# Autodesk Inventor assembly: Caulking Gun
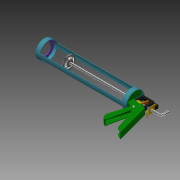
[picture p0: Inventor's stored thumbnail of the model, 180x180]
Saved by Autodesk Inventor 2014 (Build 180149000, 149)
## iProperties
Created: 2009-03
Part Number: Caulking Gun
Document SubType Name: Assembly
Designer: tangg
Mass: 1178.56 g
Surface Area: 1624.46 cm^2
Volume: 273.486 cm^3
Density: 4.30939 g/cm^3
Author: tangg
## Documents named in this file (13)
- C:\Users\iTools\Desktop\tutorial files\Stress Analysis Contacts\Caulk Gun.iam
- C:\Users\iTools\Desktop\tutorial files\Stress Analysis Contacts\Plunger.ipt
- C:\Users\iTools\Desktop\tutorial files\Stress Analysis Contacts\Main Frame.ipt
- C:\Users\iTools\Desktop\tutorial files\Stress Analysis Contacts\Handle.ipt
- C:\Users\iTools\Desktop\tutorial files\Stress Analysis Contacts\Trigger.ipt
- C:\Users\iTools\Desktop\tutorial files\Stress Analysis Contacts\Actuator.ipt
- C:\Users\iTools\Desktop\tutorial files\Stress Analysis Contacts\Caulk Tube.ipt
- C:\Users\iTools\Desktop\tutorial files\Stress Analysis Contacts\Pin.ipt
- C:\Users\iTools\Desktop\tutorial files\Stress Analysis Contacts\Actuator Spring.ipt
- C:\Users\iTools\Desktop\tutorial files\Stress Analysis Contacts\Front Frame.ipt
- C:\Users\iTools\Desktop\tutorial files\Stress Analysis Contacts\Ring.ipt
- C:\Users\iTools\Desktop\tutorial files\Stress Analysis Contacts\Lock.ipt
- C:\Users\iTools\Desktop\tutorial files\Stress Analysis Contacts\Lock Spring.ipt
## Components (12 placed, 12 different names)
1. Main Frame:1 — Flush:1, Flush:2, Flush:3, Mate:30, Flush:5, Mate:44, Flush:11, Mate:54, Mate:57, Flush:15
2. Front Frame:1 — Mate:39, Flush:11, Mate:51, Mate:58
3. Caulk Tube:1 — Mate:31
4. Handle:1 — Flush:2, Mate:27, Mate:33, Flush:5, Mate:39
5. Plunger:1 — Flush:1, Mate:27, Mate:30, Mate:31, Flush:8, Mate:43, Flush:14, Mate:49, Mate:50, Mate:53, Mate:56
6. Trigger:1 — Flush:3, Mate:34, Tangent:1, Mate:59
7. Pin:1 — Mate:33, Mate:34, Mate:59
8. Actuator:1 — Tangent:1, Flush:14, Mate:49, Mate:50
9. Actuator Spring:1 — Mate:43, Mate:44
10. Ring:1 — Mate:51, Mate:58
11. Lock:1 — Mate:56, Mate:57, Flush:15
12. Lock Spring:2 — Mate:53, Mate:54
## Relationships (26: Mate 17, Flush 8, Tangent 1)
- Flush:1: Main Frame:1 ↔ Plunger:1
- Flush:2: Main Frame:1 ↔ Handle:1
- Flush:3: Main Frame:1 ↔ Trigger:1
- Mate:27: Handle:1 ↔ Plunger:1
- Mate:30: Main Frame:1 ↔ Plunger:1
- Mate:31: Caulk Tube:1 ↔ Plunger:1
- Mate:33: Handle:1 ↔ Pin:1
- Mate:34: Trigger:1 ↔ Pin:1
- Flush:5: Main Frame:1 ↔ Handle:1
- Flush:8: Plunger:1
- Mate:39: Front Frame:1 ↔ Handle:1
- Mate:43: Plunger:1 ↔ Actuator Spring:1
- Mate:44: Main Frame:1 ↔ Actuator Spring:1
- Flush:11: Main Frame:1 ↔ Front Frame:1
- Tangent:1: Trigger:1 ↔ Actuator:1
- Flush:14: Plunger:1 ↔ Actuator:1
- Mate:49: Plunger:1 ↔ Actuator:1
- Mate:50: Plunger:1 ↔ Actuator:1
- Mate:51: Front Frame:1 ↔ Ring:1
- Mate:53: Plunger:1 ↔ Lock Spring:2
- Mate:54: Main Frame:1 ↔ Lock Spring:2
- Mate:56: Plunger:1 ↔ Lock:1
- Mate:57: Main Frame:1 ↔ Lock:1
- Flush:15: Main Frame:1 ↔ Lock:1
- Mate:58: Front Frame:1 ↔ Ring:1
- Mate:59: Trigger:1 ↔ Pin:1
## Named parameters: sa_14 = 14496.5324 mm, sa_15 = -3853.64091 mm, sa_16 = 0 mm, sa_17 = -14488.88739 mm, sa_18 = -3882.28568 mm, sa_19 = 0 mm, sa_20 = 20000 mm, sa_21 = 0, sa_22 = 0, sa_23 = -20000 mm, sa_24 = 0 mm, sa_25 = 0 mm, sa_27 = 0
